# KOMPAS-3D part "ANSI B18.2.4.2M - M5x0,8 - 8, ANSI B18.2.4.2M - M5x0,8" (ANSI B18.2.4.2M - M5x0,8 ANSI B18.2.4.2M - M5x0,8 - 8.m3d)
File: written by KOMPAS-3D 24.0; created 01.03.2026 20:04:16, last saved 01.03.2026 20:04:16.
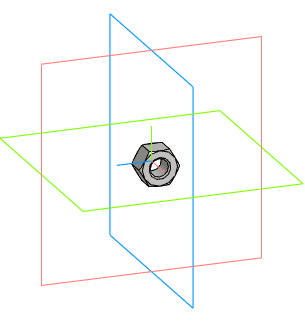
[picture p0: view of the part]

Document properties: Автор: R2D2; Полное имя файла: E:\Работа\Зайцев\GVWR3131M-2W-F-S Задвижка клиновая с выдвижным штоком DN.ru Ду50-200 Ру63\DN80\исходные материалы\ANSI B18.2.4.2M - M5x0,8 ANSI B18.2.4.2M - M5x0,8 - 8.m3d

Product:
- Body: Solid1  | qty 1
- Part/product: ANSI B18.2.4.2M - M5x0,8 - 8  | designation ANSI B18.2.4.2M - M5x0,8
    Комментарий: Типы метрических   шестигранных гаек   2
    additional columns: Сталь, мягкая

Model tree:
1. Solid1  (labels: Solid1)

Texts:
  ANSI B18.2.4.2M - M5x0,8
